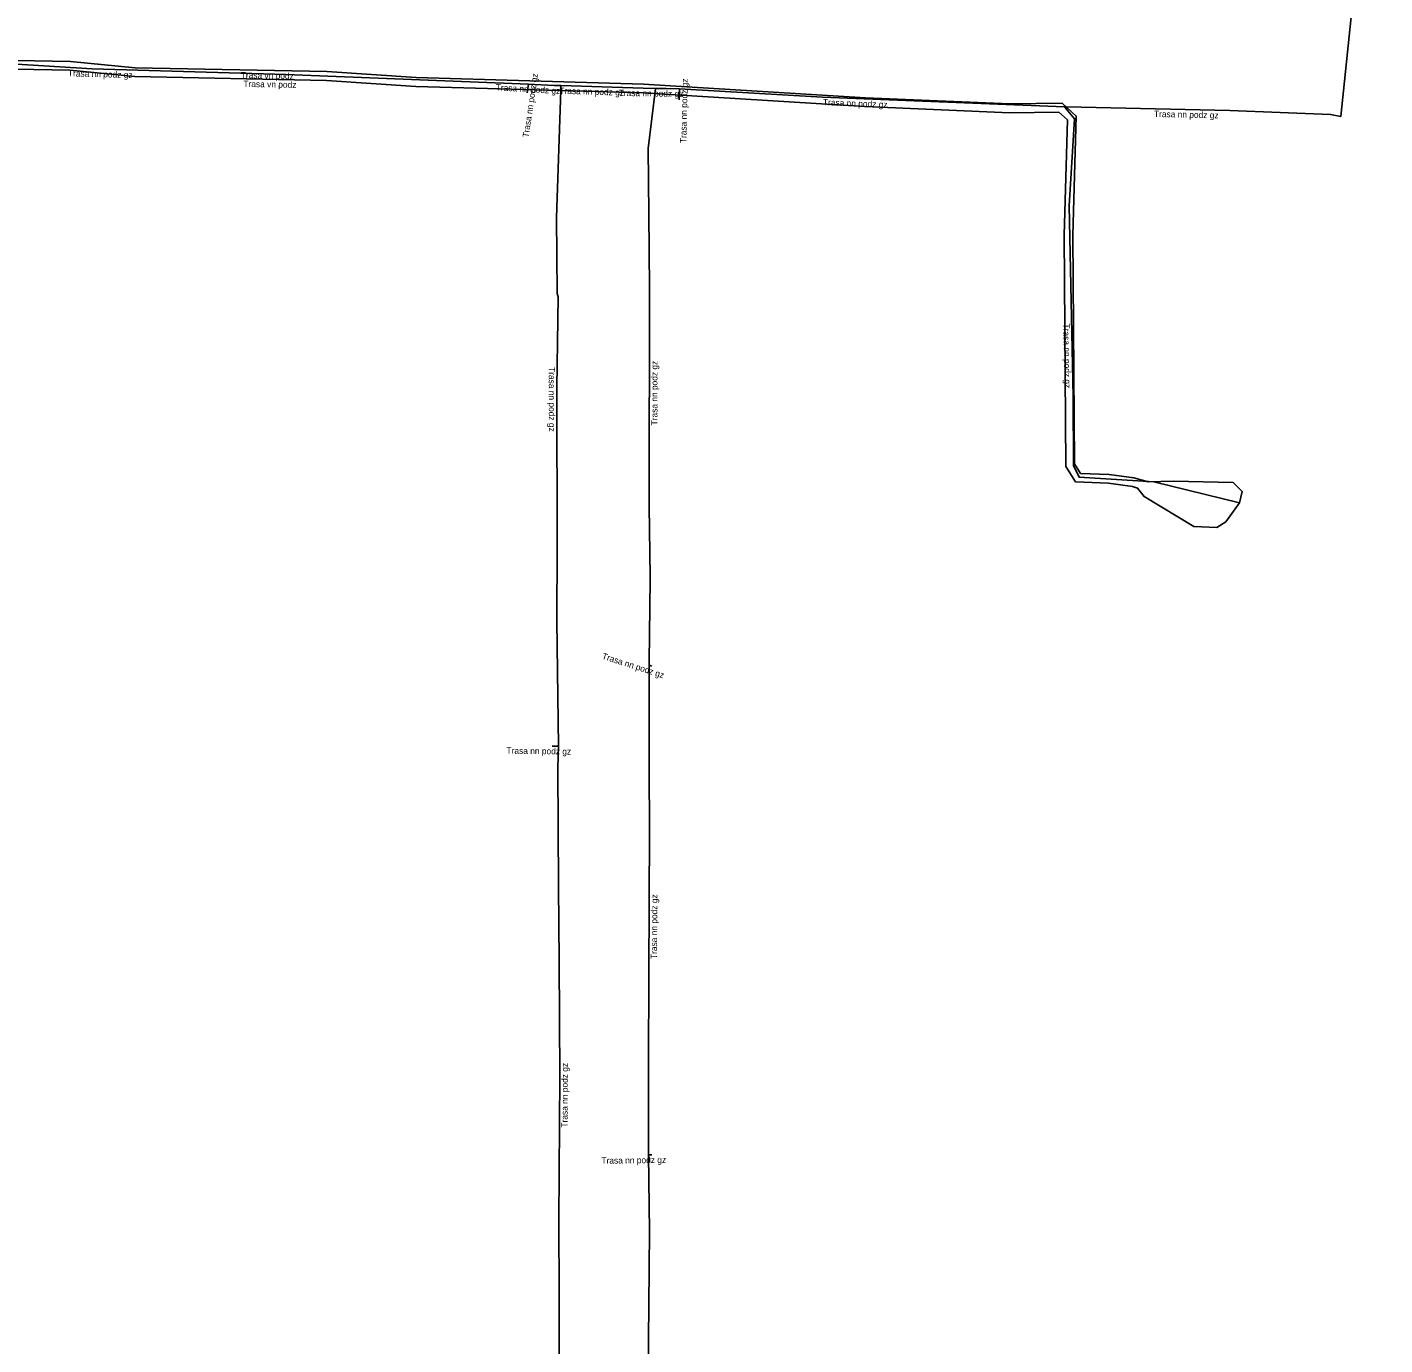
# Model space of a CAD drawing. Extents: x -747038 to -746494, y -1019526 to -1019195.
# Drawn here: x -746606.8 to -746498.3, y -1019358.2 to -1019252.9 of the extents above; entities that cross this region are included whole.
import ezdxf

# ---------------------------------------------------------------- set-up
doc = ezdxf.new("R2010")
doc.units = 0
for name, color, linetype in [('Popiskový text - Ostatní atributy Trasy', 7, 'Continuous'), ('Spojnice NN', 7, 'Continuous'), ('Spojnice VN', 7, 'Continuous')]:
    doc.layers.add(name, color=color, linetype=linetype)

msp = doc.modelspace()

# ---------------------------------------------------------------- linework, layer by layer
at = {"layer": 'Spojnice NN'}
for points in [[(-746498.3, -1019226.1), (-746501.81, -1019260.02)], [(-746566.72, -1019257.44), (-746586.08, -1019256.68), (-746601.56, -1019256.22), (-746617.48, -1019255.22), (-746632.46, -1019254.52)], [(-746566.72, -1019257.44), (-746566.82, -1019258.14)], [(-746564.12, -1019257.56), (-746564.66, -1019257.56), (-746566.72, -1019257.44)], [(-746564.32, -1019310.35), (-746564.45, -1019300.36), (-746564.42, -1019294.47), (-746564.44, -1019281.72), (-746564.33, -1019274.43), (-746564.43, -1019274.18), (-746564.48, -1019268.1), (-746564.13, -1019257.91), (-746564.12, -1019257.56)], [(-746564.12, -1019257.56), (-746557.54, -1019257.75), (-746556.56, -1019257.78)], [(-746556.56, -1019257.78), (-746557.16, -1019262.59), (-746557.09, -1019267.78), (-746557.05, -1019273.77), (-746557.06, -1019291.17), (-746556.99, -1019296.79), (-746557, -1019297.05), (-746557.07, -1019303.58), (-746557.08, -1019303.88)], [(-746554.65, -1019257.81), (-746555.75, -1019257.79), (-746556.56, -1019257.78)], [(-746554.65, -1019257.81), (-746554.68, -1019258.69)], [(-746523.9, -1019259.24), (-746543.23, -1019258.47), (-746554.65, -1019257.81)], [(-746501.81, -1019260.02), (-746502.63, -1019259.86), (-746510.68, -1019259.55), (-746522.56, -1019259.28), (-746523.9, -1019259.24)], [(-746523.9, -1019259.24), (-746523.09, -1019260.2), (-746523.53, -1019267.17), (-746523.21, -1019282.43), (-746523.17, -1019287.91), (-746522.73, -1019288.85), (-746516.76, -1019289.22), (-746509.9, -1019290.9)], [(-746557.08, -1019303.88), (-746557.08, -1019311.62), (-746557.04, -1019317.61), (-746557.06, -1019322.22), (-746557.11, -1019329.15), (-746557.12, -1019335.12), (-746557.12, -1019342.61), (-746557.12, -1019343.01)], [(-746557.08, -1019303.88), (-746556.86, -1019303.95)], [(-746564.32, -1019310.35), (-746564.81, -1019310.34)], [(-746564.25, -1019363.51), (-746564.27, -1019354.27), (-746564.28, -1019348.24), (-746564.22, -1019336.75), (-746564.27, -1019327.49), (-746564.32, -1019321.58), (-746564.38, -1019312.05), (-746564.32, -1019310.35)], [(-746557.12, -1019343.01), (-746557.04, -1019349.1), (-746557.1, -1019355.04), (-746557.16, -1019360.35), (-746557.13, -1019367.75), (-746557.17, -1019373.7), (-746557.24, -1019382.31), (-746557.24, -1019382.6)], [(-746557.12, -1019343.01), (-746556.87, -1019343.01)]]:
    msp.add_lwpolyline(points, dxfattribs=at)
at = {"layer": 'Spojnice VN'}
for points in [[(-746509.9, -1019290.9), (-746511, -1019292.41), (-746511.71, -1019292.86), (-746513.56, -1019292.79), (-746517.54, -1019290.4), (-746518.05, -1019289.73), (-746518.45, -1019289.6), (-746520.38, -1019289.32), (-746523.01, -1019289.23), (-746523.78, -1019287.99), (-746523.93, -1019269.51), (-746523.66, -1019260.29), (-746524.35, -1019259.67), (-746528.27, -1019259.72), (-746539.84, -1019259.23), (-746557.55, -1019258.14), (-746575.71, -1019257.62), (-746582.85, -1019257.14), (-746598.17, -1019256.84), (-746603.35, -1019256.32), (-746610.55, -1019256.19)], [(-746610.52, -1019255.49), (-746603.31, -1019255.62), (-746598.12, -1019256.14), (-746582.82, -1019256.44), (-746575.68, -1019256.92), (-746557.52, -1019257.44), (-746539.8, -1019258.53), (-746528.26, -1019259.02), (-746524.09, -1019258.96), (-746522.95, -1019259.99), (-746523.23, -1019269.52), (-746523.08, -1019287.79), (-746522.61, -1019288.55), (-746520.32, -1019288.62), (-746518.35, -1019288.91), (-746517.2, -1019289.21), (-746515.19, -1019289.17), (-746510.43, -1019289.27), (-746509.7, -1019289.98), (-746509.9, -1019290.9)]]:
    msp.add_lwpolyline(points, dxfattribs=at)

# ---------------------------------------------------------------- texts
at = {"layer": 'Popiskový text - Ostatní atributy Trasy'}
for s, rotation, p in [('Trasa nn podz gz', 358.3132, (-746603.51, -1019256.81)), ('Trasa vn podz', 358.8621, (-746589.7, -1019256.96)), ('Trasa vn podz', 358.863, (-746589.49, -1019257.66)), ('Trasa nn podz gz', 356.6597, (-746569.34, -1019257.93)), ('Trasa nn podz gz', 81.5374, (-746566.7, -1019261.73)), ('Trasa nn podz gz', 88.563, (-746554.11, -1019262.16)), ('Trasa nn podz gz', 358.3463, (-746564.25, -1019258.21)), ('Trasa nn podz gz', 359.0059, (-746559.51, -1019258.38)), ('Trasa nn podz gz', 357.7067, (-746543.2, -1019259.12)), ('Trasa nn podz gz', 358.6839, (-746516.75, -1019260.06)), ('Trasa nn podz gz', 271.1936, (-746523.99, -1019276.58)), ('Trasa nn podz gz', 270.0944, (-746565.09, -1019280.05)), ('Trasa nn podz gz', 89.9769, (-746556.41, -1019284.71)), ('Trasa nn podz gz', 342.2161, (-746560.88, -1019303.35)), ('Trasa nn podz gz', 359.1748, (-746568.47, -1019310.94)), ('Trasa nn podz gz', 89.5451, (-746556.45, -1019327.35)), ('Trasa nn podz gz', 89.6907, (-746563.59, -1019340.82)), ('Trasa nn podz gz', 0.7015, (-746560.88, -1019343.71))]:
    msp.add_text(s, height=0.5, rotation=rotation, dxfattribs=at).set_placement(p)

doc.saveas('drawing.dxf')
